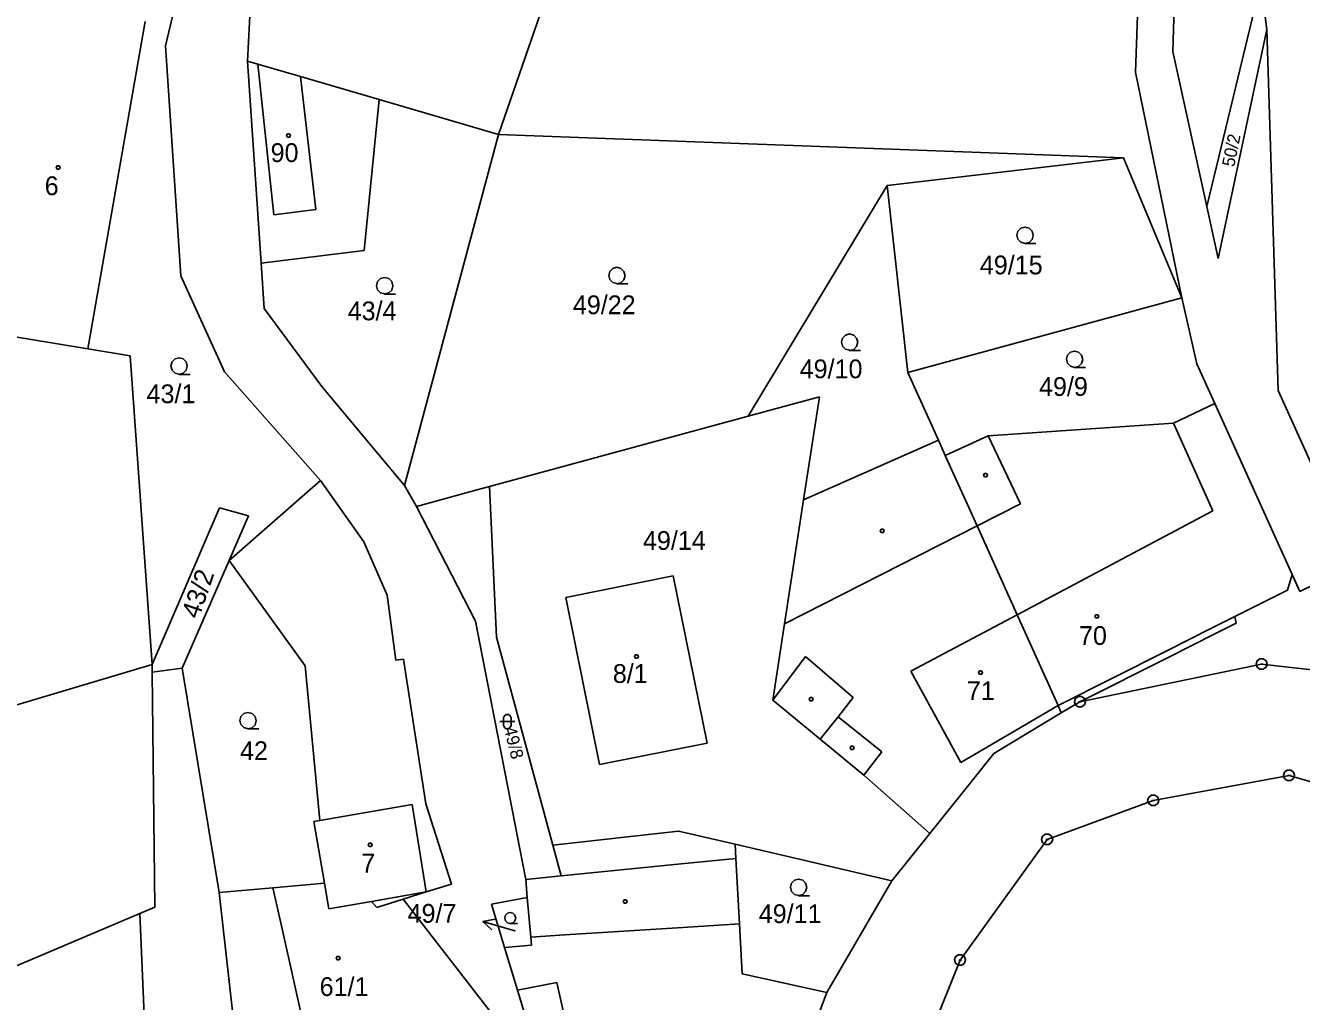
# Model space of a CAD drawing. Extents: x -779723 to -777378, y -1011169 to -1009297.
# Drawn here: x -779102 to -778986.4, y -1010209.9 to -1010121.5 of the extents above; entities that cross this region are included whole.
import ezdxf

# ---------------------------------------------------------------- set-up
doc = ezdxf.new("R2010")
doc.units = 0
for name, color, linetype in [('Default', 7, 'Continuous'), ('KN_HRANICE', 7, 'Continuous'), ('KN_KULTURY', 7, 'Continuous'), ('KN_PARCELY', 7, 'Continuous'), ('KN_SLUCKY', 7, 'Continuous')]:
    doc.layers.add(name, color=color, linetype=linetype)

# ---------------------------------------------------------------- blocks, each defined once
blk = doc.blocks.new('304')
at = {"layer": 'Default'}
blk.add_lwpolyline([(0, 0), (-0.38, 0.1), (-0.65, 0.37), (-0.75, 0.74), (-0.65, 1.11), (-0.38, 1.38), (-0.01, 1.48), (0.36, 1.38), (0.63, 1.11), (0.73, 0.73), (0.63, 0.35), (0.36, 0.08), (-0.02, -0.02), (0.98, -0.02)], dxfattribs=at)
blk = doc.blocks.new('316')
at = {"layer": 'Default'}
for points in [[(-0.5, 1.5), (-0.4, 1.79), (-0.15, 1.97), (0.16, 1.97), (0.41, 1.79), (0.51, 1.5), (0.51, 0.5), (0.41, 0.21), (0.16, 0.03), (-0.15, 0.03), (-0.4, 0.21), (-0.5, 0.5), (-0.5, 1.5)], [(-1, 1), (0.27, 1), (1, 1)]]:
    blk.add_lwpolyline(points, dxfattribs=at)
blk = doc.blocks.new('NAHRADNI_SYMBOL')
at = {"layer": 'Default'}
blk.add_lwpolyline([(0.09, 0.15), (0.18, 0), (0.09, -0.15), (-0.09, -0.15), (-0.18, 0), (-0.09, 0.15), (0.09, 0.15)], dxfattribs=at)
blk = doc.blocks.new('10292')
at = {"layer": 'Default'}
blk.add_line((0, 3), (0, 0), dxfattribs=at)
blk.add_lwpolyline([(-0.5, 2), (0, 3), (0.5, 2)], dxfattribs=at)
blk = doc.blocks.new('402')
at = {"layer": 'Default'}
blk.add_lwpolyline([(0.09, 0.15), (0.18, 0), (0.09, -0.15), (-0.09, -0.15), (-0.18, 0), (-0.09, 0.15), (0.09, 0.15)], dxfattribs=at)
blk = doc.blocks.new('105')
at = {"layer": 'Default'}
blk.add_line((-0.12, 0), (0.12, 0), dxfattribs=at)
blk.add_lwpolyline([(0.15, 0.48), (0.4, 0.3), (0.5, 0.01), (0.4, -0.28), (0.15, -0.46), (-0.16, -0.46), (-0.41, -0.28), (-0.51, 0.01), (-0.41, 0.3), (-0.16, 0.48), (0.15, 0.48)], dxfattribs=at)

msp = doc.modelspace()

# ---------------------------------------------------------------- linework, layer by layer
at = {"layer": 'KN_HRANICE'}
for p, q in [((-779000.52, -1010098.75), (-779001.45, -1010125.72)), ((-779059.16, -1010131.37), (-779049.6, -1010103.69)), ((-778998.08, -1010123.85), (-778997.43, -1010104.66)), ((-779089.32, -1010123.35), (-779086.41, -1010111.17)), ((-778990.45, -1010119.1), (-778994.99, -1010137.88)), ((-778989.56, -1010121.87), (-778989.92, -1010119.02)), ((-779081.9, -1010124.73), (-779081.62, -1010119.49)), ((-779091.18, -1010121.13), (-779096.36, -1010150.77)), ((-778989.56, -1010121.87), (-778993.95, -1010142.6)), ((-778988.54, -1010154.56), (-778989.56, -1010121.87)), ((-779089.32, -1010123.35), (-779087.92, -1010144.17)), ((-778998.08, -1010123.85), (-778994.99, -1010137.88)), ((-779081.9, -1010124.73), (-779080.97, -1010125)), ((-779080.96, -1010138.56), (-779081.9, -1010124.73)), ((-779080.97, -1010125), (-779077.09, -1010126.13)), ((-779077.09, -1010126.13), (-779069.96, -1010128.21)), ((-779001.45, -1010125.72), (-778997.25, -1010146.17)), ((-779071.34, -1010141.88), (-779069.96, -1010128.21)), ((-779069.96, -1010128.21), (-779059.16, -1010131.37)), ((-779067.67, -1010163.14), (-779059.16, -1010131.37)), ((-779059.16, -1010131.37), (-779002.53, -1010133.47)), ((-779023.96, -1010136), (-779002.53, -1010133.47)), ((-778997.25, -1010146.17), (-779002.53, -1010133.47)), ((-779023.96, -1010136), (-779036.53, -1010156.87)), ((-779022.06, -1010152.93), (-779023.96, -1010136)), ((-778994.99, -1010137.88), (-778993.95, -1010142.6)), ((-779080.66, -1010143.03), (-779080.96, -1010138.56)), ((-779080.66, -1010143.03), (-779071.34, -1010141.88)), ((-779080.38, -1010147.12), (-779080.66, -1010143.03)), ((-779087.92, -1010144.17), (-779083.99, -1010152.87)), ((-779080.38, -1010147.12), (-779075.16, -1010154.2)), ((-779022.06, -1010152.93), (-778997.25, -1010146.17)), ((-778995.89, -1010152.14), (-778997.25, -1010146.17)), ((-779096.36, -1010150.77), (-779108.53, -1010148.76)), ((-779092.51, -1010151.41), (-779096.36, -1010150.77)), ((-779090.53, -1010179.36), (-779092.51, -1010151.41)), ((-779083.99, -1010152.87), (-779075.29, -1010162.7)), ((-779019.31, -1010159.04), (-779022.06, -1010152.93)), ((-778995.89, -1010152.14), (-778994.26, -1010155.74)), ((-779075.16, -1010154.2), (-779067.67, -1010163.14)), ((-779036.53, -1010156.87), (-779030.09, -1010155.12)), ((-779031.52, -1010164.45), (-779030.09, -1010155.12)), ((-778988.54, -1010154.56), (-778981.44, -1010170.24)), ((-778998.02, -1010157.51), (-778994.26, -1010155.74)), ((-778994.26, -1010155.74), (-778987.25, -1010171.2)), ((-779059.96, -1010163.24), (-779036.53, -1010156.87)), ((-779014.8, -1010158.67), (-778998.02, -1010157.51)), ((-779018.68, -1010160.43), (-779014.8, -1010158.67)), ((-779031.52, -1010164.45), (-779019.31, -1010159.04)), ((-779018.68, -1010160.43), (-779019.31, -1010159.04)), ((-779015.8, -1010166.81), (-779018.68, -1010160.43)), ((-779083.57, -1010169.95), (-779075.29, -1010162.7)), ((-779075.29, -1010162.7), (-779071.35, -1010168.24)), ((-779067.67, -1010163.14), (-779066.59, -1010165.05)), ((-779060.89, -1010163.49), (-779059.96, -1010163.24)), ((-779059.96, -1010163.24), (-779059.34, -1010176.89)), ((-779066.59, -1010165.05), (-779060.89, -1010163.49)), ((-779033.24, -1010175.69), (-779031.52, -1010164.45)), ((-779090.53, -1010179.36), (-779084.42, -1010165.17)), ((-779084.42, -1010165.17), (-779081.81, -1010165.89)), ((-779066.59, -1010165.05), (-779061.23, -1010175.43)), ((-779083.57, -1010169.95), (-779081.81, -1010165.89)), ((-779012.17, -1010174.86), (-779015.8, -1010166.81)), ((-779071.35, -1010168.24), (-779069.24, -1010173.07)), ((-779087.81, -1010179.7), (-779083.57, -1010169.95)), ((-779083.57, -1010169.95), (-779076.68, -1010179.47)), ((-778986.55, -1010172.74), (-778981.44, -1010170.24)), ((-779043.34, -1010171.33), (-779053.06, -1010173.29)), ((-779043.34, -1010171.33), (-779040.25, -1010186.48)), ((-778987.25, -1010171.2), (-778987.68, -1010172.63)), ((-778987.25, -1010171.2), (-778986.55, -1010172.74)), ((-778992.44, -1010175.02), (-778987.68, -1010172.63)), ((-779068.46, -1010178.97), (-779069.24, -1010173.07)), ((-779053.06, -1010173.29), (-779050, -1010188.42)), ((-779008.46, -1010183.09), (-779012.17, -1010174.86)), ((-779057.23, -1010196.04), (-779061.23, -1010175.43)), ((-779034.3, -1010182.59), (-779033.24, -1010175.69)), ((-778992.32, -1010175.62), (-778994.25, -1010176.59)), ((-778992.44, -1010175.02), (-778992.32, -1010175.62)), ((-779054.24, -1010195.71), (-779059.34, -1010176.89)), ((-778994.25, -1010176.59), (-778998.36, -1010178.66)), ((-779127.44, -1010190.39), (-779090.53, -1010179.36)), ((-779090.52, -1010180.07), (-779090.53, -1010179.36)), ((-779075.35, -1010193.49), (-779076.68, -1010179.47)), ((-779067.77, -1010178.88), (-779068.46, -1010178.97)), ((-779067.77, -1010178.88), (-779065.75, -1010191.98)), ((-778998.36, -1010178.66), (-779006.48, -1010182.74)), ((-778990.02, -1010179.33), (-779006.48, -1010182.74)), ((-778990.02, -1010179.33), (-778987.62, -1010179.6)), ((-779090.52, -1010180.07), (-779087.81, -1010179.7)), ((-779090.29, -1010201.34), (-779090.52, -1010180.07)), ((-779087.81, -1010179.7), (-779084.45, -1010200.01)), ((-778987.62, -1010179.6), (-778970.48, -1010181.53)), ((-779030.01, -1010186.12), (-779034.3, -1010182.59)), ((-779008.17, -1010183.75), (-779006.48, -1010182.74)), ((-779014.29, -1010187.42), (-779008.17, -1010183.75)), ((-779008.17, -1010183.75), (-779008.46, -1010183.09)), ((-779050, -1010188.42), (-779040.25, -1010186.48)), ((-779026.06, -1010189.37), (-779030.01, -1010186.12)), ((-779016.32, -1010189.95), (-779014.29, -1010187.42)), ((-779026.06, -1010189.37), (-779020.62, -1010194.19)), ((-779020.09, -1010194.66), (-779016.32, -1010189.95)), ((-778999.84, -1010191.68), (-778987.54, -1010189.4)), ((-778987.54, -1010189.4), (-778972.6, -1010193.75)), ((-779063.41, -1010199.24), (-779065.75, -1010191.98)), ((-779009.45, -1010195.21), (-778999.84, -1010191.68)), ((-779075.89, -1010193.58), (-779075.35, -1010193.49)), ((-779074.93, -1010199.16), (-779075.89, -1010193.58)), ((-779054.24, -1010195.71), (-779042.86, -1010194.45)), ((-779037.72, -1010195.64), (-779042.86, -1010194.45)), ((-779020.62, -1010194.19), (-779020.09, -1010194.66)), ((-779053.48, -1010198.51), (-779054.24, -1010195.71)), ((-779023.53, -1010198.94), (-779037.72, -1010195.64)), ((-779037.72, -1010195.64), (-779037.65, -1010196.93)), ((-779023.53, -1010198.94), (-779020.09, -1010194.66)), ((-779017.34, -1010206.13), (-779009.45, -1010195.21)), ((-779056.69, -1010198.83), (-779057.23, -1010196.04)), ((-779037.65, -1010196.93), (-779037.33, -1010202.84)), ((-779079.59, -1010199.58), (-779074.93, -1010199.16)), ((-779074.53, -1010201.5), (-779074.93, -1010199.16)), ((-779056.69, -1010198.83), (-779053.48, -1010198.51)), ((-779056.69, -1010198.83), (-779056.55, -1010200.46)), ((-779023.53, -1010198.94), (-779029.4, -1010209.06)), ((-779084.45, -1010200.01), (-779079.59, -1010199.58)), ((-779078.76, -1010203.29), (-779079.59, -1010199.58)), ((-779067.78, -1010200.61), (-779065.7, -1010199.95)), ((-779065.7, -1010199.95), (-779063.41, -1010199.24)), ((-779091.64, -1010201.91), (-779090.29, -1010201.34)), ((-779070.67, -1010200.83), (-779074.53, -1010201.5)), ((-779070.67, -1010200.83), (-779070.18, -1010201.36)), ((-779070.18, -1010201.36), (-779067.78, -1010200.61)), ((-779067.78, -1010200.61), (-779062.19, -1010207.85)), ((-779059.79, -1010201.08), (-779056.55, -1010200.46)), ((-779059.79, -1010201.08), (-779058.6, -1010204.99)), ((-779056.55, -1010200.46), (-779056.24, -1010204.04)), ((-779106.91, -1010208.39), (-779091.64, -1010201.91)), ((-779089.99, -1010242.37), (-779091.64, -1010201.91)), ((-779076.2, -1010214.76), (-779078.76, -1010203.29)), ((-779037.33, -1010202.84), (-779037.09, -1010207.36)), ((-779058.6, -1010204.99), (-779056.17, -1010204.79)), ((-779058.6, -1010204.99), (-779057.43, -1010208.85)), ((-779056.24, -1010204.04), (-779056.17, -1010204.79)), ((-779023.92, -1010222.47), (-779017.34, -1010206.13)), ((-779062.19, -1010207.85), (-779059.7, -1010211.07)), ((-779029.4, -1010209.06), (-779037.09, -1010207.36)), ((-779057.43, -1010208.85), (-779056.71, -1010211.24)), ((-779033.8, -1010220.65), (-779029.4, -1010209.06))]:
    msp.add_line(p, q, dxfattribs=at)
msp.add_lwpolyline([(-779084.45, -1010200.01), (-779081.11, -1010229.82), (-779079.62, -1010236.77)], dxfattribs=at)
at = {"layer": 'KN_PARCELY'}
msp.add_line((-779057.66, -1010203.49), (-779057.69, -1010203.48), dxfattribs=at)
at = {"layer": 'KN_SLUCKY'}
for p, q in [((-779080.97, -1010125), (-779079.51, -1010138.63)), ((-779077.09, -1010126.13), (-779075.69, -1010138.16)), ((-779079.51, -1010138.63), (-779075.69, -1010138.16)), ((-778998.02, -1010157.51), (-778994.45, -1010165.45)), ((-779011.87, -1010164.81), (-779014.8, -1010158.67)), ((-779015.8, -1010166.81), (-779011.87, -1010164.81)), ((-779002.7, -1010169.83), (-778994.45, -1010165.45)), ((-779033.24, -1010175.69), (-779015.8, -1010166.81)), ((-779012.17, -1010174.86), (-779002.7, -1010169.83)), ((-779021.79, -1010179.97), (-779012.17, -1010174.86)), ((-778994.55, -1010176.08), (-778998.62, -1010178.13)), ((-778992.44, -1010175.02), (-778994.55, -1010176.08)), ((-778998.62, -1010178.13), (-779008.46, -1010183.09)), ((-779034.3, -1010182.59), (-779031.34, -1010178.65)), ((-779031.34, -1010178.65), (-779027.03, -1010182.36)), ((-779017.26, -1010188.23), (-779021.79, -1010179.97)), ((-779027.03, -1010182.36), (-779028.4, -1010184.09)), ((-779028.4, -1010184.09), (-779030.01, -1010186.12)), ((-779028.4, -1010184.09), (-779024.42, -1010187.27)), ((-779008.46, -1010183.09), (-779017.26, -1010188.23)), ((-779026.06, -1010189.37), (-779024.42, -1010187.27)), ((-779075.35, -1010193.49), (-779066.99, -1010192.05)), ((-779066.99, -1010192.05), (-779065.7, -1010199.95)), ((-779053.48, -1010198.51), (-779042.9, -1010197.45)), ((-779042.9, -1010197.45), (-779037.65, -1010196.93)), ((-779065.7, -1010199.95), (-779070.67, -1010200.83)), ((-779056.24, -1010204.04), (-779053.16, -1010203.85)), ((-779053.16, -1010203.85), (-779042.47, -1010203.17)), ((-779042.47, -1010203.17), (-779037.33, -1010202.84)), ((-779057.43, -1010208.85), (-779053.86, -1010208.15)), ((-779053.86, -1010208.15), (-779053.04, -1010211.92))]:
    msp.add_line(p, q, dxfattribs=at)

# ---------------------------------------------------------------- block references
at = {"layer": 'KN_KULTURY'}
for name, p in [('402', (-779078.18, -1010131.47)), ('402', (-779099.06, -1010134.35)), ('304', (-779011.45, -1010141.23)), ('304', (-779048.42, -1010144.87)), ('304', (-779069.46, -1010145.8)), ('304', (-779027.34, -1010150.91)), ('304', (-779088.08, -1010153.07)), ('304', (-779006.96, -1010152.46)), ('402', (-779015.03, -1010162.21)), ('402', (-779024.39, -1010167.26)), ('402', (-779004.95, -1010175)), ('402', (-779046.66, -1010178.63)), ('402', (-779015.48, -1010180.1)), ('402', (-779030.84, -1010182.51)), ('304', (-779081.84, -1010185.18)), ('402', (-779027.12, -1010186.92)), ('402', (-779070.78, -1010195.69)), ('304', (-779031.96, -1010200.28)), ('402', (-779047.68, -1010200.82)), ('NAHRADNI_SYMBOL', (-779073.69, -1010205.95))]:
    msp.add_blockref(name, p, dxfattribs=at)
at = {"layer": 'KN_KULTURY', "xscale": 0.67, "yscale": 0.67}
for name, p in [('316', (-779058.36, -1010185.2)), ('304', (-779058.09, -1010202.81))]:
    msp.add_blockref(name, p, dxfattribs=at)
at = {"layer": 'KN_PARCELY'}
for p in [(-778990.02, -1010179.33), (-779006.48, -1010182.74), (-778987.54, -1010189.4), (-778999.84, -1010191.68), (-779009.45, -1010195.21), (-779017.34, -1010206.13)]:
    msp.add_blockref('105', p, dxfattribs=at)
at = {"layer": 'KN_PARCELY', "rotation": 73.395894}
msp.add_blockref('10292', (-779057.69, -1010203.48), dxfattribs=at)

# ---------------------------------------------------------------- texts
at = {"layer": 'KN_PARCELY'}
for s, height, p in [('90', 1.7, (-779079.8, -1010133.86)), ('6', 1.7, (-779100.27, -1010136.86)), ('49/15', 1.7, (-779015.55, -1010144.03)), ('49/22', 1.7, (-779052.42, -1010147.64)), ('43/4', 1.7, (-779072.82, -1010148.19)), ('49/10', 1.7, (-779031.87, -1010153.44)), ('43/1', 1.7, (-779091.04, -1010155.7)), ('49/9', 1.7, (-779010.19, -1010155.04)), ('49/14', 1.7, (-779046.07, -1010168.98)), ('70', 1.7, (-779006.57, -1010177.59)), ('8/1', 1.7, (-779048.8, -1010181.03)), ('71', 1.7, (-779016.73, -1010182.59)), ('42', 1.7, (-779082.57, -1010188.02)), ('7', 1.7, (-779071.59, -1010198.2)), ('49/7', 1.7, (-779067.39, -1010202.75)), ('49/11', 1.7, (-779035.58, -1010202.78)), ('49/7', 0.1, (-779057.86, -1010203.49)), ('61/1', 1.7, (-779075.36, -1010209.38))]:
    msp.add_text(s, height=height, dxfattribs=at).set_placement(p)
for s, height, rotation, p in [('50/2', 1.14, 78.553, (-778992.51, -1010134.36)), ('43/2', 1.7, 70.932, (-779086.32, -1010175.31)), ('49/8', 1.14, 284.015, (-779058.68, -1010185.14))]:
    msp.add_text(s, height=height, rotation=rotation, dxfattribs=at).set_placement(p)

doc.saveas('drawing.dxf')
